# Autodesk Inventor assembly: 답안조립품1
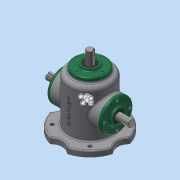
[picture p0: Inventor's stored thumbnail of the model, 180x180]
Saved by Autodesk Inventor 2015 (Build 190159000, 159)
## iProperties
Created: 2022-04
Part Number: 답안조립품1
Document SubType Name: Assembly
Designer: User
Author: User
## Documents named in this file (16)
- C:\Users\User\Desktop\720406V1005\답안조립품1.iam
- C:\Users\User\Desktop\720406V1005\부품1.ipt
- C:\Users\User\Desktop\720406V1005\메인 베벨기어.ipt
- C:\Users\User\Desktop\720406V1005\메인 축.ipt
- 메인 축.ipt
- C:\Users\User\Desktop\720406V1005\베어링 6203.ipt
- C:\Users\User\Desktop\720406V1005\볼트 M4.ipt
- 볼트 M4.ipt
- C:\Users\User\Desktop\720406V1005\서브 베벨기어.ipt
- C:\Users\User\Desktop\720406V1005\서브 축.ipt
- 서브 축.ipt
- C:\Users\User\Desktop\720406V1005\오일 실.ipt
- 오일 실.ipt
- C:\Users\User\Desktop\720406V1005\커버.ipt
- C:\Users\User\Desktop\720406V1005\키 4x4.ipt
- C:\Users\User\Desktop\720406V1005\키 5x5.ipt
